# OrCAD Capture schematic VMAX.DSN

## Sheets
1 PAGE1: size A
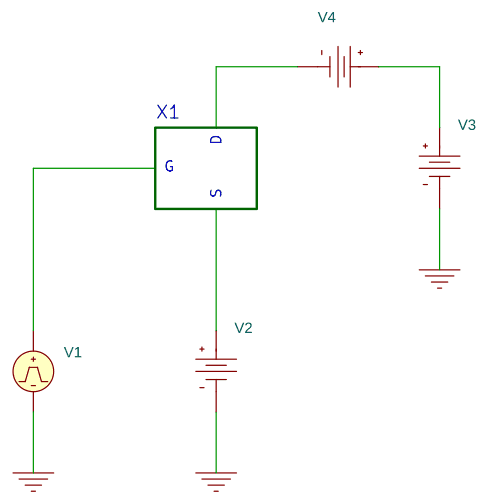
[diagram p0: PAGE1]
2 PAGE1 (2): size A; block X1
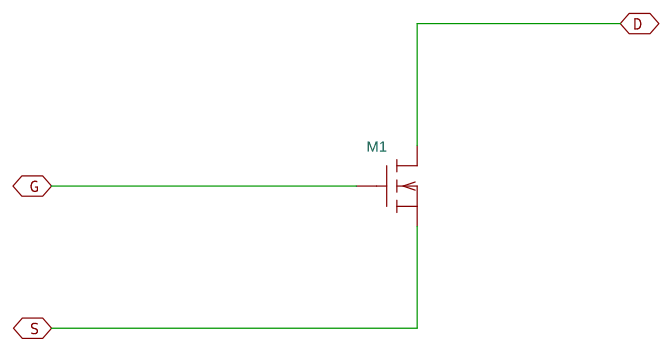
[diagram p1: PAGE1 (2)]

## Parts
sheet PAGE1 (2)
M1  MbreakN3
sheet PAGE1
V1  VPULSE
V2  VDC
V3  VDC
V4  VDC

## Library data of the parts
M1 = MbreakN3
V1 = VPULSE: PER: 100n; PW: 50n; TD: 1n; TF: 1n; TR: 1n; V1: 0; V2: 10
V2-V4 = VDC

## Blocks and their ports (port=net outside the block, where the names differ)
X1 = schematic Mosfet1, on sheet PAGE1: S=N00041, G=N00031, D=N00044

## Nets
0: V1.2(-) V2.1(-) V3.1(-)
N00031: M1.1(g) V1.1(+)
N00041: M1.0(s) V2.0(+)
N00044: M1.2(d) V4.1(-)
N00051: V3.0(+) V4.0(+)
